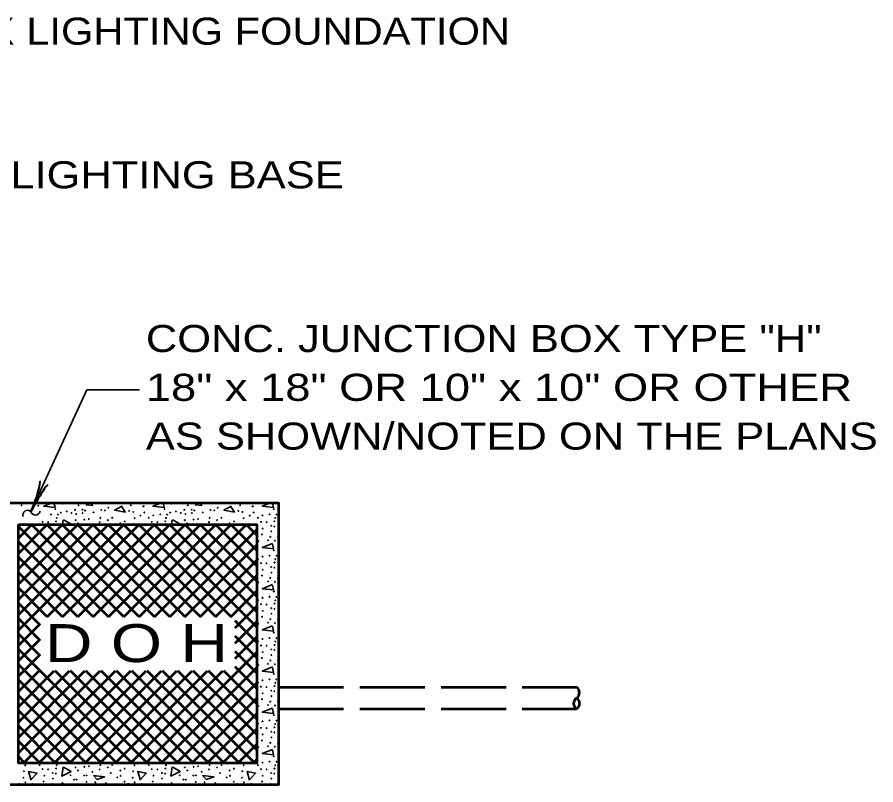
# Model space of a CAD drawing. Extents: x -1 to 679, y 0 to 440.
# Drawn here: x 391.4 to 470.6, y 78.6 to 149.4 of the extents above; entities that cross this region are included whole.
import ezdxf
from ezdxf.enums import TextEntityAlignment as Align

# ---------------------------------------------------------------- set-up
doc = ezdxf.new("R2010")
doc.units = 0
doc.linetypes.add('LONG_DASHED', pattern=[7.5, 6, -1.5])
doc.layers.add('1', color=7, linetype='Continuous', lineweight=35)

msp = doc.modelspace()

# ---------------------------------------------------------------- linework, layer by layer
at = {"layer": '1'}
for p, q in [((392.647, 103.805), (397.796, 115.046)), ((402.654, 115.046), (397.796, 115.046)), ((395.546, 102.608), (395.61, 103.056)), ((405.626, 102.608), (405.69, 103.056))]:
    msp.add_line(p, q, dxfattribs=at)
at = {"layer": '1', "lineweight": 53}
for p, q in [((391.486, 101.358), (392.736, 102.608)), ((391.486, 99.944), (394.15, 102.608)), ((391.486, 98.53), (395.564, 102.608)), ((391.486, 97.115), (396.979, 102.608)), ((391.486, 95.701), (398.393, 102.608)), ((391.486, 94.287), (399.807, 102.608)), ((391.486, 92.873), (401.221, 102.608)), ((399.795, 94.108), (391.486, 102.418)), ((401.21, 94.108), (392.71, 102.608)), ((402.624, 94.108), (394.124, 102.608)), ((394.135, 94.108), (402.635, 102.608)), ((404.038, 94.108), (395.538, 102.608)), ((395.55, 94.108), (404.05, 102.608)), ((405.452, 94.108), (396.952, 102.608)), ((396.964, 94.108), (405.464, 102.608)), ((406.866, 94.108), (398.366, 102.608)), ((398.378, 94.108), (406.878, 102.608)), ((408.281, 94.108), (399.781, 102.608)), ((399.792, 94.108), (408.292, 102.608)), ((409.695, 94.108), (401.195, 102.608)), ((401.207, 94.108), (409.707, 102.608)), ((411.109, 94.108), (402.609, 102.608)), ((402.621, 94.108), (411.121, 102.608)), ((413.486, 93.146), (404.023, 102.608)), ((404.035, 94.108), (412.535, 102.608)), ((413.486, 94.56), (405.438, 102.608)), ((413.486, 95.974), (406.852, 102.608)), ((413.486, 97.388), (408.266, 102.608)), ((413.486, 98.803), (409.68, 102.608)), ((413.486, 100.217), (411.094, 102.608)), ((413.486, 101.631), (412.509, 102.608)), ((405.449, 94.108), (413.486, 102.145)), ((398.381, 94.108), (391.486, 101.004)), ((406.863, 94.108), (413.486, 100.731)), ((396.967, 94.108), (391.486, 99.589)), ((408.278, 94.108), (413.486, 99.317)), ((395.553, 94.108), (391.486, 98.175)), ((409.692, 94.108), (413.486, 97.902)), ((394.138, 94.108), (391.486, 96.761)), ((411.106, 94.108), (413.486, 96.488)), ((393.486, 93.347), (391.486, 95.347)), ((411.486, 93.074), (413.486, 95.074)), ((393.486, 91.933), (391.486, 93.933)), ((413.486, 91.732), (411.486, 93.732)), ((411.486, 91.66), (413.486, 93.66)), ((391.486, 91.459), (393.486, 93.459)), ((393.486, 90.518), (391.486, 92.518)), ((391.486, 90.044), (393.486, 92.044)), ((413.486, 90.317), (411.486, 92.317)), ((411.486, 90.245), (413.486, 92.245)), ((401.982, 80.608), (391.486, 91.104)), ((391.486, 88.63), (393.486, 90.63)), ((403.263, 80.608), (413.486, 90.831)), ((413.486, 88.903), (411.486, 90.903)), ((400.567, 80.608), (391.486, 89.69)), ((391.486, 87.216), (393.486, 89.216)), ((391.486, 85.802), (394.792, 89.108)), ((391.486, 84.388), (396.207, 89.108)), ((391.486, 82.973), (397.621, 89.108)), ((391.486, 81.559), (399.035, 89.108)), ((391.949, 80.608), (400.449, 89.108)), ((393.363, 80.608), (401.863, 89.108)), ((394.778, 80.608), (403.278, 89.108)), ((403.396, 80.608), (394.896, 89.108)), ((396.192, 80.608), (404.692, 89.108)), ((404.81, 80.608), (396.31, 89.108)), ((397.606, 80.608), (406.106, 89.108)), ((406.224, 80.608), (397.724, 89.108)), ((399.02, 80.608), (407.52, 89.108)), ((407.638, 80.608), (399.138, 89.108)), ((400.435, 80.608), (408.935, 89.108)), ((409.053, 80.608), (400.553, 89.108)), ((401.849, 80.608), (410.349, 89.108)), ((410.467, 80.608), (401.967, 89.108)), ((411.881, 80.608), (403.381, 89.108)), ((404.677, 80.608), (413.486, 89.417)), ((413.295, 80.608), (404.795, 89.108)), ((413.486, 81.832), (406.21, 89.108)), ((413.486, 83.246), (407.624, 89.108)), ((413.486, 84.66), (409.038, 89.108)), ((413.486, 86.075), (410.452, 89.108)), ((413.486, 87.489), (411.486, 89.489)), ((399.153, 80.608), (391.486, 88.276)), ((406.091, 80.608), (413.486, 88.003)), ((397.739, 80.608), (391.486, 86.861)), ((407.506, 80.608), (413.486, 86.589)), ((396.325, 80.608), (391.486, 85.447)), ((408.92, 80.608), (413.486, 85.174)), ((394.911, 80.608), (391.486, 84.033)), ((410.334, 80.608), (413.486, 83.76)), ((393.496, 80.608), (391.486, 82.619)), ((411.748, 80.608), (413.486, 82.346)), ((392.082, 80.608), (391.486, 81.205)), ((413.162, 80.608), (413.486, 80.932))]:
    msp.add_line(p, q, dxfattribs=at)
at = {"layer": '1', "linetype": 'LONG_DASHED', "lineweight": 53}
for p, q in [((415.486, 87.608), (442.986, 87.608)), ((415.486, 85.608), (442.986, 85.608))]:
    msp.add_line(p, q, dxfattribs=at)
at = {"layer": '1', "lineweight": 53}
for points in [[(389.486, 78.608), (389.486, 104.608), (415.486, 104.608), (415.486, 78.608)], [(391.486, 102.608), (413.486, 102.608), (413.486, 80.608), (391.486, 80.608)]]:
    msp.add_lwpolyline(points, close=True, dxfattribs=at)
at = {"layer": '1'}
for points in [[(394.602, 104.608), (393.83, 104.296), (394.87, 104.176), (394.776, 104.608)], [(397.933, 104.608), (397.75, 104.416), (398.33, 104.376), (398.214, 104.608)], [(404.682, 104.608), (403.91, 104.296), (404.95, 104.176), (404.856, 104.608)], [(408.012, 104.608), (407.83, 104.416), (408.41, 104.376), (408.294, 104.608)], [(414.762, 104.608), (413.99, 104.296), (415.03, 104.176), (414.936, 104.608)], [(401.03, 104.296), (400.37, 103.936), (401.35, 103.756), (400.99, 104.316)], [(411.11, 104.296), (410.45, 103.936), (411.43, 103.756), (411.07, 104.316)], [(395.65, 103.036), (396.35, 102.636), (396.293, 102.608)], [(405.73, 103.036), (406.43, 102.636), (406.373, 102.608)], [(392.438, 102.608), (392.43, 102.636), (392.566, 102.608)], [(402.518, 102.608), (402.51, 102.636), (402.646, 102.608)], [(412.598, 102.608), (412.59, 102.636), (412.726, 102.608)], [(414.93, 100.876), (413.99, 100.496), (415.03, 100.376), (414.93, 100.836)], [(414.93, 97.076), (413.99, 96.696), (415.03, 96.576), (414.93, 97.036)], [(414.93, 93.276), (413.99, 92.896), (415.03, 92.776), (414.93, 93.236)], [(414.93, 89.476), (413.99, 89.096), (415.03, 88.976), (414.93, 89.436)], [(414.93, 85.676), (413.99, 85.296), (415.03, 85.176), (414.93, 85.636)], [(414.93, 81.876), (413.99, 81.496), (415.03, 81.376), (414.93, 81.836)], [(395.65, 80.236), (396.35, 79.836), (395.49, 79.416), (395.61, 80.256)], [(405.73, 80.236), (406.43, 79.836), (405.57, 79.416), (405.69, 80.256)], [(392.67, 79.036), (392.43, 79.836), (393.21, 79.676), (392.65, 79.076)], [(402.75, 79.036), (402.51, 79.836), (403.29, 79.676), (402.73, 79.076)], [(412.83, 79.036), (412.59, 79.836), (413.37, 79.676), (412.81, 79.076)]]:
    msp.add_lwpolyline(points, dxfattribs=at)
for points in [[(398.41, 79.456), (399.45, 79.336), (398.77, 79.096)], [(408.49, 79.456), (409.53, 79.336), (408.85, 79.096)]]:
    msp.add_lwpolyline(points, close=True, dxfattribs=at)
for centre in [(395.534, 104.555), (396.369, 104.568), (405.614, 104.555), (406.449, 104.568), (391.784, 104.396), (392.923, 104.303), (393.315, 104.345), (394.898, 104.038), (395.945, 103.826), (396.714, 103.972), (397.045, 104.383), (397.403, 103.985), (397.636, 103.906), (399.133, 103.959), (399.478, 103.919), (399.796, 104.158), (401.705, 103.866), (401.864, 104.396), (402.089, 103.773), (403.003, 104.303), (403.056, 104.303), (404.978, 104.038), (406.025, 103.826), (406.794, 103.972), (407.125, 104.383), (407.483, 103.985), (407.716, 103.906), (409.213, 103.959), (409.558, 103.919), (409.876, 104.158), (411.785, 103.866), (411.944, 104.396), (412.169, 103.773), (413.083, 104.303), (413.136, 104.303), (415.058, 104.038), (394.5, 103.548), (395.031, 103.216), (395.137, 103.534), (395.415, 103.707), (396.396, 103.68), (396.767, 103.017), (396.82, 103.574), (397.416, 103.667), (397.575, 103.07), (397.994, 103.123), (398.418, 103.733), (399.054, 103.229), (399.743, 103.017), (400.141, 103.229), (402.208, 103.203), (402.752, 103.442), (403.123, 103.72), (403.52, 103.229), (403.931, 103.455), (404.58, 103.548), (405.111, 103.216), (405.217, 103.534), (405.495, 103.707), (406.476, 103.68), (406.847, 103.017), (406.9, 103.574), (407.496, 103.667), (407.655, 103.07), (408.074, 103.123), (408.498, 103.733), (409.134, 103.229), (409.823, 103.017), (410.221, 103.229), (412.288, 103.203), (412.832, 103.442), (413.203, 103.72), (413.6, 103.229), (414.011, 103.455), (414.66, 103.548), (415.191, 103.216), (415.297, 103.534), (391.996, 102.659), (393.719, 102.858), (394.235, 102.832), (394.964, 102.911), (396.992, 102.726), (399.001, 102.832), (400.896, 102.726), (401.307, 102.898), (402.076, 102.659), (403.799, 102.858), (404.315, 102.832), (405.044, 102.911), (407.072, 102.726), (409.081, 102.832), (410.976, 102.726), (411.387, 102.898), (412.156, 102.659), (413.879, 102.858), (414.038, 102.248), (414.395, 102.832), (414.819, 102.5), (415.111, 102.434), (415.124, 102.911), (413.971, 101.705), (414.74, 101.48), (414.833, 101.983), (415.442, 101.453), (413.64, 101.073), (414.528, 101.166), (415.164, 101.126), (415.058, 100.238), (413.6, 99.429), (413.879, 99.058), (414.011, 99.655), (414.395, 99.032), (414.66, 99.748), (415.124, 99.111), (415.191, 99.416), (415.297, 99.734), (414.038, 98.448), (414.819, 98.7), (415.111, 98.634), (413.971, 97.905), (414.74, 97.68), (414.833, 98.183), (415.442, 97.653), (413.64, 97.273), (414.528, 97.366), (415.164, 97.326), (414.011, 95.855), (414.66, 95.948), (415.058, 96.438), (415.297, 95.934), (413.6, 95.629), (413.879, 95.258), (414.395, 95.232), (415.124, 95.311), (415.191, 95.616), (414.038, 94.648), (414.819, 94.9), (414.833, 94.383), (415.111, 94.834), (413.64, 93.473), (413.971, 94.105), (414.528, 93.566), (414.74, 93.88), (415.164, 93.526), (415.442, 93.853), (414.011, 92.055), (414.66, 92.148), (415.058, 92.638), (415.297, 92.134), (413.6, 91.829), (413.879, 91.458), (414.395, 91.432), (414.819, 91.1), (415.124, 91.511), (415.191, 91.816), (413.971, 90.305), (414.038, 90.848), (414.833, 90.583), (415.111, 91.034), (413.64, 89.673), (414.528, 89.766), (414.74, 90.08), (415.164, 89.726), (415.442, 90.053), (415.058, 88.838), (413.6, 88.029), (414.011, 88.255), (414.66, 88.348), (415.191, 88.016), (415.297, 88.334), (413.879, 87.658), (414.395, 87.632), (414.819, 87.3), (415.111, 87.234), (415.124, 87.711), (413.971, 86.505), (414.038, 87.048), (414.833, 86.783), (413.64, 85.873), (414.528, 85.966), (414.74, 86.28), (415.164, 85.926), (415.442, 86.253), (415.058, 85.038), (413.6, 84.229), (414.011, 84.455), (414.66, 84.548), (415.191, 84.216), (415.297, 84.534), (413.879, 83.858), (414.038, 83.248), (414.395, 83.832), (414.819, 83.5), (415.111, 83.434), (415.124, 83.911), (413.971, 82.705), (414.74, 82.48), (414.833, 82.983), (415.442, 82.453), (413.64, 82.073), (414.528, 82.166), (415.164, 82.126), (415.058, 81.238), (392.128, 80.403), (393.44, 80.429), (393.719, 80.058), (394.235, 80.032), (394.964, 80.111), (395.031, 80.416), (396.767, 80.217), (397.575, 80.27), (397.994, 80.323), (399.001, 80.032), (399.054, 80.429), (399.743, 80.217), (400.141, 80.429), (401.307, 80.098), (402.208, 80.403), (403.52, 80.429), (403.799, 80.058), (404.315, 80.032), (405.044, 80.111), (405.111, 80.416), (406.847, 80.217), (407.655, 80.27), (408.074, 80.323), (409.081, 80.032), (409.134, 80.429), (409.823, 80.217), (410.221, 80.429), (411.387, 80.098), (412.288, 80.403), (413.6, 80.429), (413.879, 80.058), (414.011, 80.655), (414.395, 80.032), (414.66, 80.748), (415.124, 80.111), (415.191, 80.416), (415.297, 80.734), (391.956, 79.263), (391.996, 79.859), (393.878, 79.448), (394.659, 79.7), (394.951, 79.634), (396.303, 79.488), (396.992, 79.926), (397.555, 79.459), (397.782, 79.475), (398.325, 79.806), (400.021, 79.7), (400.618, 79.289), (400.896, 79.926), (400.936, 79.435), (402.036, 79.263), (402.076, 79.859), (403.958, 79.448), (404.739, 79.7), (405.031, 79.634), (406.383, 79.488), (407.072, 79.926), (407.635, 79.459), (407.862, 79.475), (408.405, 79.806), (410.101, 79.7), (410.698, 79.289), (410.976, 79.926), (411.016, 79.435), (412.116, 79.263), (412.156, 79.859), (414.038, 79.448), (414.819, 79.7), (415.111, 79.634), (391.558, 78.693), (392.141, 78.839), (392.791, 78.693), (393.811, 78.905), (394.58, 78.68), (394.673, 79.183), (395.282, 78.653), (395.561, 78.772), (396.634, 79.09), (396.86, 79.09), (397.782, 78.878), (398.59, 78.839), (399.584, 78.759), (401.28, 78.892), (401.638, 78.693), (402.221, 78.839), (402.871, 78.693), (403.891, 78.905), (404.66, 78.68), (404.753, 79.183), (405.362, 78.653), (405.641, 78.772), (406.714, 79.09), (406.94, 79.09), (407.862, 78.878), (408.67, 78.839), (409.664, 78.759), (411.36, 78.892), (411.718, 78.693), (412.301, 78.839), (412.951, 78.693), (413.971, 78.905), (414.74, 78.68), (414.833, 79.183), (415.442, 78.653)]:
    msp.add_circle(centre, 0.0265, dxfattribs=at)
for centre, radius, start, end in [((391.624, 104.608), 0.0265, 179.8468, 0.1532), ((392.3, 104.608), 0.0265, 179.8468, 0.1532), ((401.704, 104.608), 0.0265, 179.8468, 0.1532), ((402.38, 104.608), 0.0265, 179.8468, 0.1532), ((411.784, 104.608), 0.0265, 179.8468, 0.1532), ((412.46, 104.608), 0.0265, 179.8468, 0.1532), ((392.344, 103.488), 0.439, 46.31832, 196.9194), ((393.068, 103.93), 0.439, 196.46709, 347.06816), ((398.325, 102.606), 0.0265, 4.24531, 175.75469), ((408.405, 102.606), 0.0265, 4.24531, 175.75469), ((396.343, 78.587), 0.0265, 54.86427, 125.13573), ((397.323, 78.6), 0.0265, 18.43349, 161.56651), ((406.423, 78.587), 0.0265, 54.86427, 125.13573), ((407.403, 78.6), 0.0265, 18.43349, 161.56651)]:
    msp.add_arc(centre, radius, start, end, dxfattribs=at)
at = {"layer": '1', "lineweight": 53}
for centre, radius, start, end in [((442.678, 87.108), 0.587, 301.63189, 58.3681), ((443.333, 86.108), 0.609, 124.76549, 235.23451), ((442.704, 86.108), 0.574, 299.39122, 60.60878)]:
    msp.add_arc(centre, radius, start, end, dxfattribs=at)
at = {"layer": '1', "lineweight": 40}
for centre, major_axis, ratio, start_param, end_param in [((392.85, 104.912), (-0.602, -1.688), 0.122415, 0.896353, 3.141593), ((392.85, 104.912), (-0.602, -1.688), 0.122415, 0.896353, 3.141593), ((393.306, 104.736), (-0.891, -1.524), 0.07063, 3.140715, 5.41811), ((393.306, 104.736), (-0.891, -1.524), 0.07063, 3.140715, 5.41811)]:
    msp.add_ellipse(centre, major_axis=major_axis, ratio=ratio, start_param=start_param, end_param=end_param, dxfattribs=at)

# ---------------------------------------------------------------- texts
at = {"layer": '1'}
for s, height, width, p in [('TYPE X LIGHTING FOUNDATION', 2.5, 1.15, (407.164, 146.868)), ('TYPE X LIGHTING BASE', 2.5, 1.2, (398.435, 133.62)), ('D O H', 3.5, 1.3, (402.384, 89.926))]:
    msp.add_text(s, height=height, dxfattribs=dict(at, width=width)).set_placement(p, align=Align.CENTER)
for s, width, p in [('CONC. JUNCTION BOX TYPE "H"', 1.2, (403.251, 118.519)), ('18" x 18" OR 10" x 10" OR OTHER', 1.25, (403.251, 114.019)), ('AS SHOWN/NOTED ON THE PLANS ', 1.2, (403.251, 109.519))]:
    msp.add_text(s, height=2.5, dxfattribs=dict(at, width=width)).set_placement(p)

doc.saveas('drawing.dxf')
